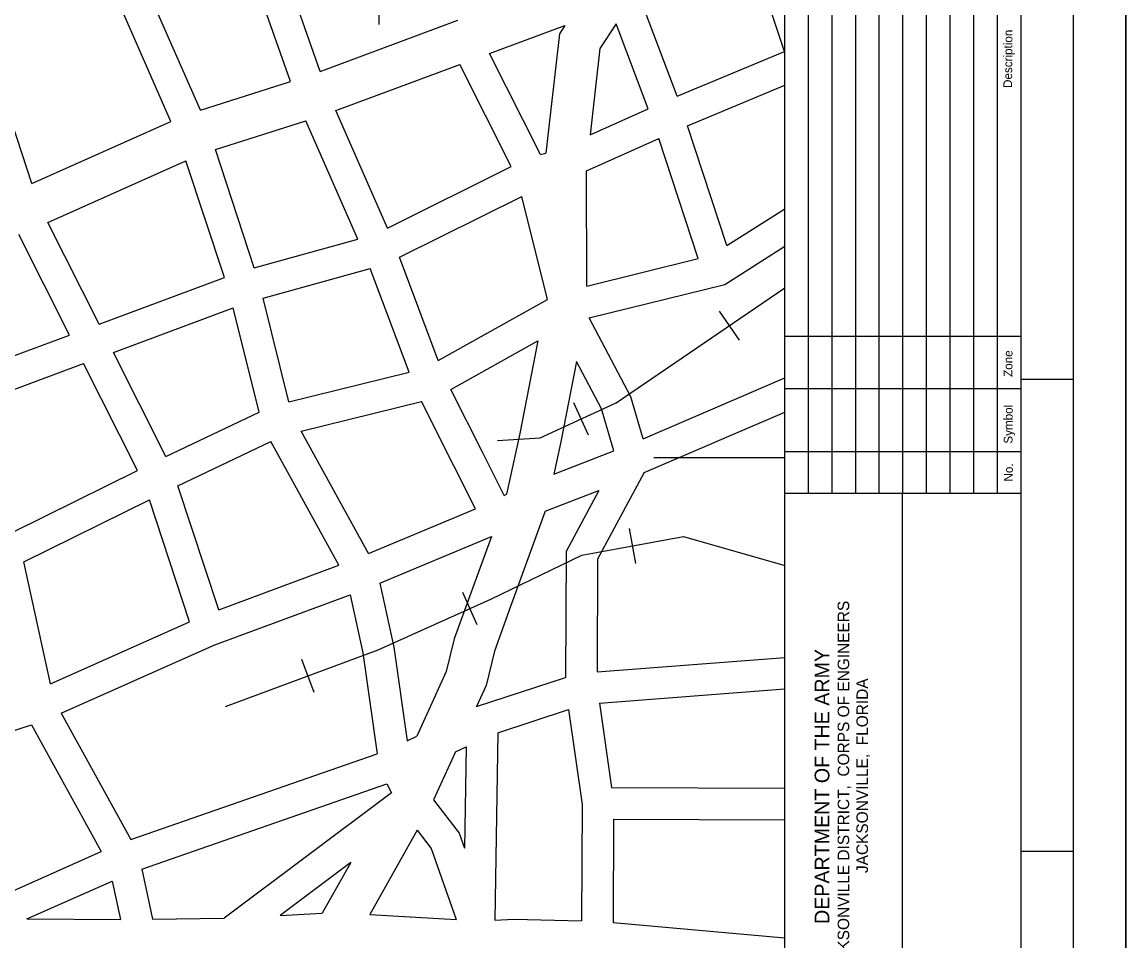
# Model space of a CAD drawing. Extents: x 503330 to 511530, y 1310349 to 1316149.
# Drawn here: x 509426 to 511530, y 1313078 to 1314830 of the extents above; entities that cross this region are included whole.
import ezdxf

# ---------------------------------------------------------------- set-up
doc = ezdxf.new("R2010")
doc.units = 0
for name, color, linetype in [('G-ANNO-TEXT', 7, 'Continuous'), ('G-ANNO-TTLB', 7, 'Continuous'), ('Level 2', 7, 'Continuous'), ('Level 23', 7, 'Continuous'), ('Level 32', 7, 'Continuous'), ('Level 37', 7, 'Continuous')]:
    doc.layers.add(name, color=color, linetype=linetype)

msp = doc.modelspace()

# ---------------------------------------------------------------- linework, layer by layer
at = {"layer": 'G-ANNO-TTLB'}
for p, q in [((511430.3, 1310448.5), (511430.3, 1316048.5)), ((510880.3, 1310548.5), (510880.3, 1315948.5)), ((511330.3, 1315948.5), (511330.3, 1310548.5)), ((510925.3, 1313931.1), (510925.3, 1315530.9)), ((510970.3, 1313931.1), (510970.3, 1315530.9)), ((511015.3, 1313931.1), (511015.3, 1315530.9)), ((511060.3, 1313931.1), (511060.3, 1315530.9)), ((511105.3, 1313931.1), (511105.3, 1315530.9)), ((511150.3, 1313931.1), (511150.3, 1315530.9)), ((511195.3, 1313931.1), (511195.3, 1315530.9)), ((511240.3, 1313931.1), (511240.3, 1315530.9)), ((511285.3, 1313931.1), (511285.3, 1315530.9)), ((510880.3, 1314231.1), (511330.3, 1314231.1)), ((511430.3, 1314148.5), (511330.3, 1314148.5)), ((510880.3, 1314131.1), (511330.3, 1314131.1)), ((510880.3, 1314011.1), (511330.3, 1314011.1)), ((511103.7, 1313931.1), (511103.7, 1312891.3)), ((511430.3, 1313248.5), (511330.3, 1313248.5))]:
    msp.add_line(p, q, dxfattribs=at)
for points in [[(503330.3, 1310348.5), (511530.3, 1310348.5), (511530.3, 1316148.5), (503330.3, 1316148.5)], [(503330.3, 1310348.5), (511530.3, 1310348.5), (511530.3, 1316148.5), (503330.3, 1316148.5)], [(503330.3, 1316148.5), (511530.3, 1316148.5), (511530.3, 1310348.5), (503330.3, 1310348.5)]]:
    msp.add_lwpolyline(points, close=True, dxfattribs=at)
msp.add_lwpolyline([(511330.3, 1313931.1), (510880.3, 1313931.1)], dxfattribs=at)
at = {"layer": 'Level 2'}
for p, q in [((510107.1, 1314824.8), (510107.1, 1315424.8)), ((510630.3, 1314000), (510880.3, 1314000))]:
    msp.add_line(p, q, dxfattribs=at)
at = {"layer": 'Level 23'}
for p, q in [((509994.9, 1314735.8), (510257, 1314833.1)), ((510317.3, 1314770.1), (510461.2, 1314823.5)), ((510024.3, 1314661.4), (510260.7, 1314749.1)), ((509766.3, 1314661.7), (509938.1, 1314716.3)), ((509445.3, 1314522), (509710.2, 1314640.1)), ((509794.8, 1314586.8), (509967.4, 1314641.6)), ((509475.7, 1314447.9), (509738.7, 1314565.2)), ((510502.7, 1314326.6), (510502.5, 1314545.9)), ((510409.5, 1314221.8), (510374.9, 1314045.5)), ((510483.3, 1314182.8), (510453.3, 1314029.3)), ((510374.9, 1314045.5), (510349.9, 1313929.5)), ((510453.3, 1314029.3), (510440, 1313967.9)), ((510423.7, 1313897.2), (510357.5, 1313715.7)), ((510321.1, 1313849.3), (510282.4, 1313743.2)), ((510252.7, 1313438.3), (510210.5, 1313346.9)), ((510179.3, 1313289.2), (510089.2, 1313128.8)), ((510052.8, 1313227.4), (509998.5, 1313130.8))]:
    msp.add_line(p, q, dxfattribs=at)
for points in [[(510461.2, 1314823.5), (510450.5, 1314807.4), (510433.4, 1314658.3), (510424.5, 1314580.1)], [(510558.9, 1314826.4), (510527.8, 1314779.3), (510512.9, 1314649.2), (510508.9, 1314614.6)], [(510282.3, 1313743), (510250.3, 1313653.9), (510235, 1313591.6), (510210.6, 1313538.2), (510178.6, 1313468.7)], [(510357.6, 1313715.9), (510327, 1313630.7), (510310.9, 1313565.2), (510292.6, 1313524.9)]]:
    msp.add_lwpolyline(points, dxfattribs=at)
at = {"layer": 'Level 32'}
for p, q in [((509994.9, 1314735.8), (509825.9, 1315217.1)), ((509938.1, 1314716.3), (509770.5, 1315193.7)), ((509766.3, 1314661.7), (509569.4, 1315109.6)), ((509710.2, 1314640.1), (509514, 1315086.5)), ((510879.4, 1314773.8), (510806.8, 1314994.4)), ((510675, 1314688.4), (510602.7, 1314880.5)), ((510619.8, 1314664.5), (510558.9, 1314826.4)), ((509445.3, 1314522), (509363.4, 1314771)), ((510414.5, 1314577), (510317.3, 1314770.1)), ((510675, 1314688.4), (510879.3, 1314773.8)), ((510358.8, 1314554.1), (510260.7, 1314749.1)), ((510695, 1314631.8), (510880.3, 1314709.2)), ((510122.9, 1314437.1), (510024.3, 1314661.4)), ((510508.9, 1314614.6), (510619.8, 1314664.5)), ((510066.6, 1314415.9), (509967.4, 1314641.6)), ((510770, 1314403.6), (510695, 1314631.8)), ((510502.5, 1314545.9), (510639.8, 1314607.7)), ((510715, 1314378.9), (510639.8, 1314607.7)), ((509869, 1314361.1), (509794.8, 1314586.8)), ((509812, 1314342.6), (509738.7, 1314565.2)), ((510414.5, 1314577), (510424.5, 1314580.1)), ((510122.9, 1314437.1), (510358.8, 1314554.1)), ((510145.7, 1314381.4), (510379.1, 1314497.2)), ((510428.1, 1314300.9), (510379.1, 1314497.2)), ((510770, 1314403.6), (510880.3, 1314474)), ((509573.3, 1314254), (509475.7, 1314447.9)), ((509516.7, 1314233), (509420.1, 1314425)), ((509869, 1314361.1), (510066.6, 1314415.9)), ((510765.6, 1314329.6), (510880.3, 1314402.8)), ((510219.8, 1314184.6), (510145.7, 1314381.4)), ((510502.7, 1314326.6), (510715, 1314378.9)), ((509885.7, 1314303.4), (510089.6, 1314360)), ((510164, 1314162.5), (510089.6, 1314360)), ((509573.3, 1314254), (509812, 1314342.6)), ((510507.2, 1314265.9), (510765.6, 1314329.6)), ((509935, 1314106.1), (509885.7, 1314303.4)), ((510219.8, 1314184.6), (510428.1, 1314300.9)), ((509600.4, 1314200.1), (509828.5, 1314284.7)), ((509878.1, 1314086.3), (509828.5, 1314284.7)), ((510586.9, 1314115.1), (510507.2, 1314265.9)), ((509282.3, 1314146), (509516.7, 1314233)), ((510243.7, 1314129.2), (510409.5, 1314221.8)), ((509700.3, 1314001.3), (509600.4, 1314200.1)), ((509307.8, 1314091.5), (509543.8, 1314179.1)), ((509646.4, 1313975), (509543.8, 1314179.1)), ((510531, 1314092.4), (510483.3, 1314182.8)), ((509935, 1314106.1), (510164, 1314162.5)), ((510610.2, 1314035.5), (510880.3, 1314151.3)), ((510303.8, 1314009.6), (510243.7, 1314129.2)), ((509958.2, 1314050), (510187.9, 1314106.6)), ((510250.2, 1313982.6), (510187.9, 1314106.6)), ((510610.2, 1314035.5), (510586.9, 1314115.1)), ((509700.3, 1314001.3), (509878.1, 1314086.3)), ((510554.4, 1314012.5), (510531, 1314092.4)), ((510612.3, 1313971.1), (510880.3, 1314086)), ((510086.8, 1313816.4), (509958.2, 1314050)), ((509723.5, 1313945.9), (509900.5, 1314030.5)), ((510030.4, 1313794.4), (509900.5, 1314030.5)), ((510345.3, 1313927.1), (510303.8, 1314009.6)), ((510440, 1313967.9), (510554.4, 1314012.5)), ((510290.9, 1313901.7), (510250.2, 1313982.6)), ((509410.4, 1313858.1), (509646.4, 1313975)), ((510612.3, 1313971.1), (510523.3, 1313805.6)), ((509801.3, 1313709.3), (509723.5, 1313945.9)), ((510423.7, 1313897.2), (510525.8, 1313937)), ((510525.8, 1313937), (510463.4, 1313820.8)), ((509429.9, 1313800.7), (509669, 1313919.3)), ((509745.6, 1313686.7), (509669, 1313919.3)), ((510345.3, 1313927.1), (510349.9, 1313929.5)), ((510086.8, 1313816.4), (510290.9, 1313901.7)), ((510108.1, 1313760.3), (510321.1, 1313849.3)), ((510463.4, 1313820.8), (510462.5, 1313580.4)), ((509480.5, 1313568.5), (509429.9, 1313800.7)), ((509801.3, 1313709.3), (510030.4, 1313794.4)), ((510523.3, 1313805.6), (510522.5, 1313591.1)), ((510108.1, 1313760.3), (510134.8, 1313638.2)), ((509793.9, 1313642.6), (510051.5, 1313738.2)), ((510051.5, 1313738.2), (510075.7, 1313627.5)), ((509480.5, 1313568.5), (509745.6, 1313686.7)), ((509778, 1313635.4), (509793.9, 1313642.6)), ((509501.1, 1313512), (509777.9, 1313635.4)), ((510075.7, 1313627.5), (510103.5, 1313434.8)), ((510134.8, 1313638.2), (510160.5, 1313459.7)), ((510522.5, 1313591.1), (510880.3, 1313618.5)), ((510292.4, 1313524.8), (510462.5, 1313580.4)), ((510526.7, 1313531.2), (510880.3, 1313558.4)), ((510292.6, 1313524.9), (510292.2, 1313524.7)), ((510333.2, 1313475), (510467.8, 1313519.1)), ((510467.8, 1313519.1), (510493.9, 1313338.3)), ((510526.7, 1313531.2), (510549.9, 1313370.3)), ((509501.1, 1313512), (509633.5, 1313271.4)), ((509243.5, 1313426.2), (509444.7, 1313490.1)), ((509444.7, 1313490.1), (509577.4, 1313248.8)), ((510333.2, 1313475), (510327.4, 1313118)), ((510160.5, 1313459.7), (510178.6, 1313468.7)), ((509633.5, 1313271.4), (510103.5, 1313434.8)), ((510252.7, 1313438.3), (510272.8, 1313448.2)), ((510272.8, 1313448.2), (510269.7, 1313255)), ((509654.4, 1313215.1), (510121.9, 1313377.7)), ((510121.9, 1313377.7), (510130.5, 1313360.7)), ((510549.9, 1313370.3), (510880.3, 1313369.1)), ((510130.5, 1313360.7), (509811.5, 1313121.3)), ((510210.5, 1313346.9), (510259.7, 1313283.3)), ((510493.9, 1313338.3), (510493, 1313116.6)), ((510553.8, 1313310.3), (510553, 1313113.3)), ((510553.8, 1313310.3), (510880.3, 1313309.1)), ((510179.3, 1313289.2), (510206.3, 1313254.3)), ((510259.7, 1313283.3), (510269.7, 1313255)), ((509287.5, 1313119.5), (509577.4, 1313248.8)), ((510206.3, 1313254.3), (510253.7, 1313119.3)), ((510052.8, 1313227.4), (509918.5, 1313126.6)), ((509654.4, 1313215.1), (509675.3, 1313119.5)), ((509435.8, 1313120), (509598, 1313192.3)), ((509598, 1313192.3), (509613.9, 1313119.3)), ((509435.8, 1313120), (509613.9, 1313119.3)), ((509675.3, 1313119.5), (509811.5, 1313121.3)), ((509918.5, 1313126.6), (509998.5, 1313130.8)), ((510089.2, 1313128.8), (510253.7, 1313119.3)), ((510553, 1313113.3), (510880.3, 1313083.8))]:
    msp.add_line(p, q, dxfattribs=at)
msp.add_lwpolyline([(510327.4, 1313118), (510363.8, 1313119.5), (510493, 1313116.6)], dxfattribs=at)
at = {"layer": 'Level 37'}
for p, q in [((510793.8, 1314223.3), (510755.8, 1314278.9)), ((510506.2, 1314042.5), (510478.1, 1314103.8)), ((510596.5, 1313797.9), (510584.4, 1313864.1)), ((510294, 1313680.9), (510266.4, 1313742.3)), ((509982.9, 1313551.5), (509959.5, 1313614.6))]:
    msp.add_line(p, q, dxfattribs=at)
for points in [[(510332.7, 1314031.9), (510414.1, 1314037.4), (510559, 1314103.8), (510880.3, 1314323.2)], [(509814.2, 1313524.8), (510105.2, 1313632.8), (510320, 1313729.5), (510493.3, 1313813.2), (510687.2, 1313848.8), (510880.3, 1313793.7)]]:
    msp.add_lwpolyline(points, dxfattribs=at)

# ---------------------------------------------------------------- texts
at = {"layer": 'G-ANNO-TEXT'}
for s, height, rotation, p in [('Description', 16.598, 89.6609, (511313.3, 1314704.1)), ('Zone', 16.6, 89.6609, (511313.9, 1314153.3)), ('Symbol', 16.6, 89.6609, (511314.1, 1314026.1)), ('No.', 16.6, 89.6609, (511314.7, 1313953.9)), ('JACKSONVILLE DISTRICT,  CORPS OF ENGINEERS', 21.998, 90, (511002.9, 1313004.1)), ('DEPARTMENT OF THE ARMY', 27.998, 90, (510965.1, 1313110.5)), ('JACKSONVILLE,  FLORIDA', 21.998, 90, (511038.7, 1313207.5))]:
    msp.add_text(s, height=height, rotation=rotation, dxfattribs=at).set_placement(p)

doc.saveas('drawing.dxf')
